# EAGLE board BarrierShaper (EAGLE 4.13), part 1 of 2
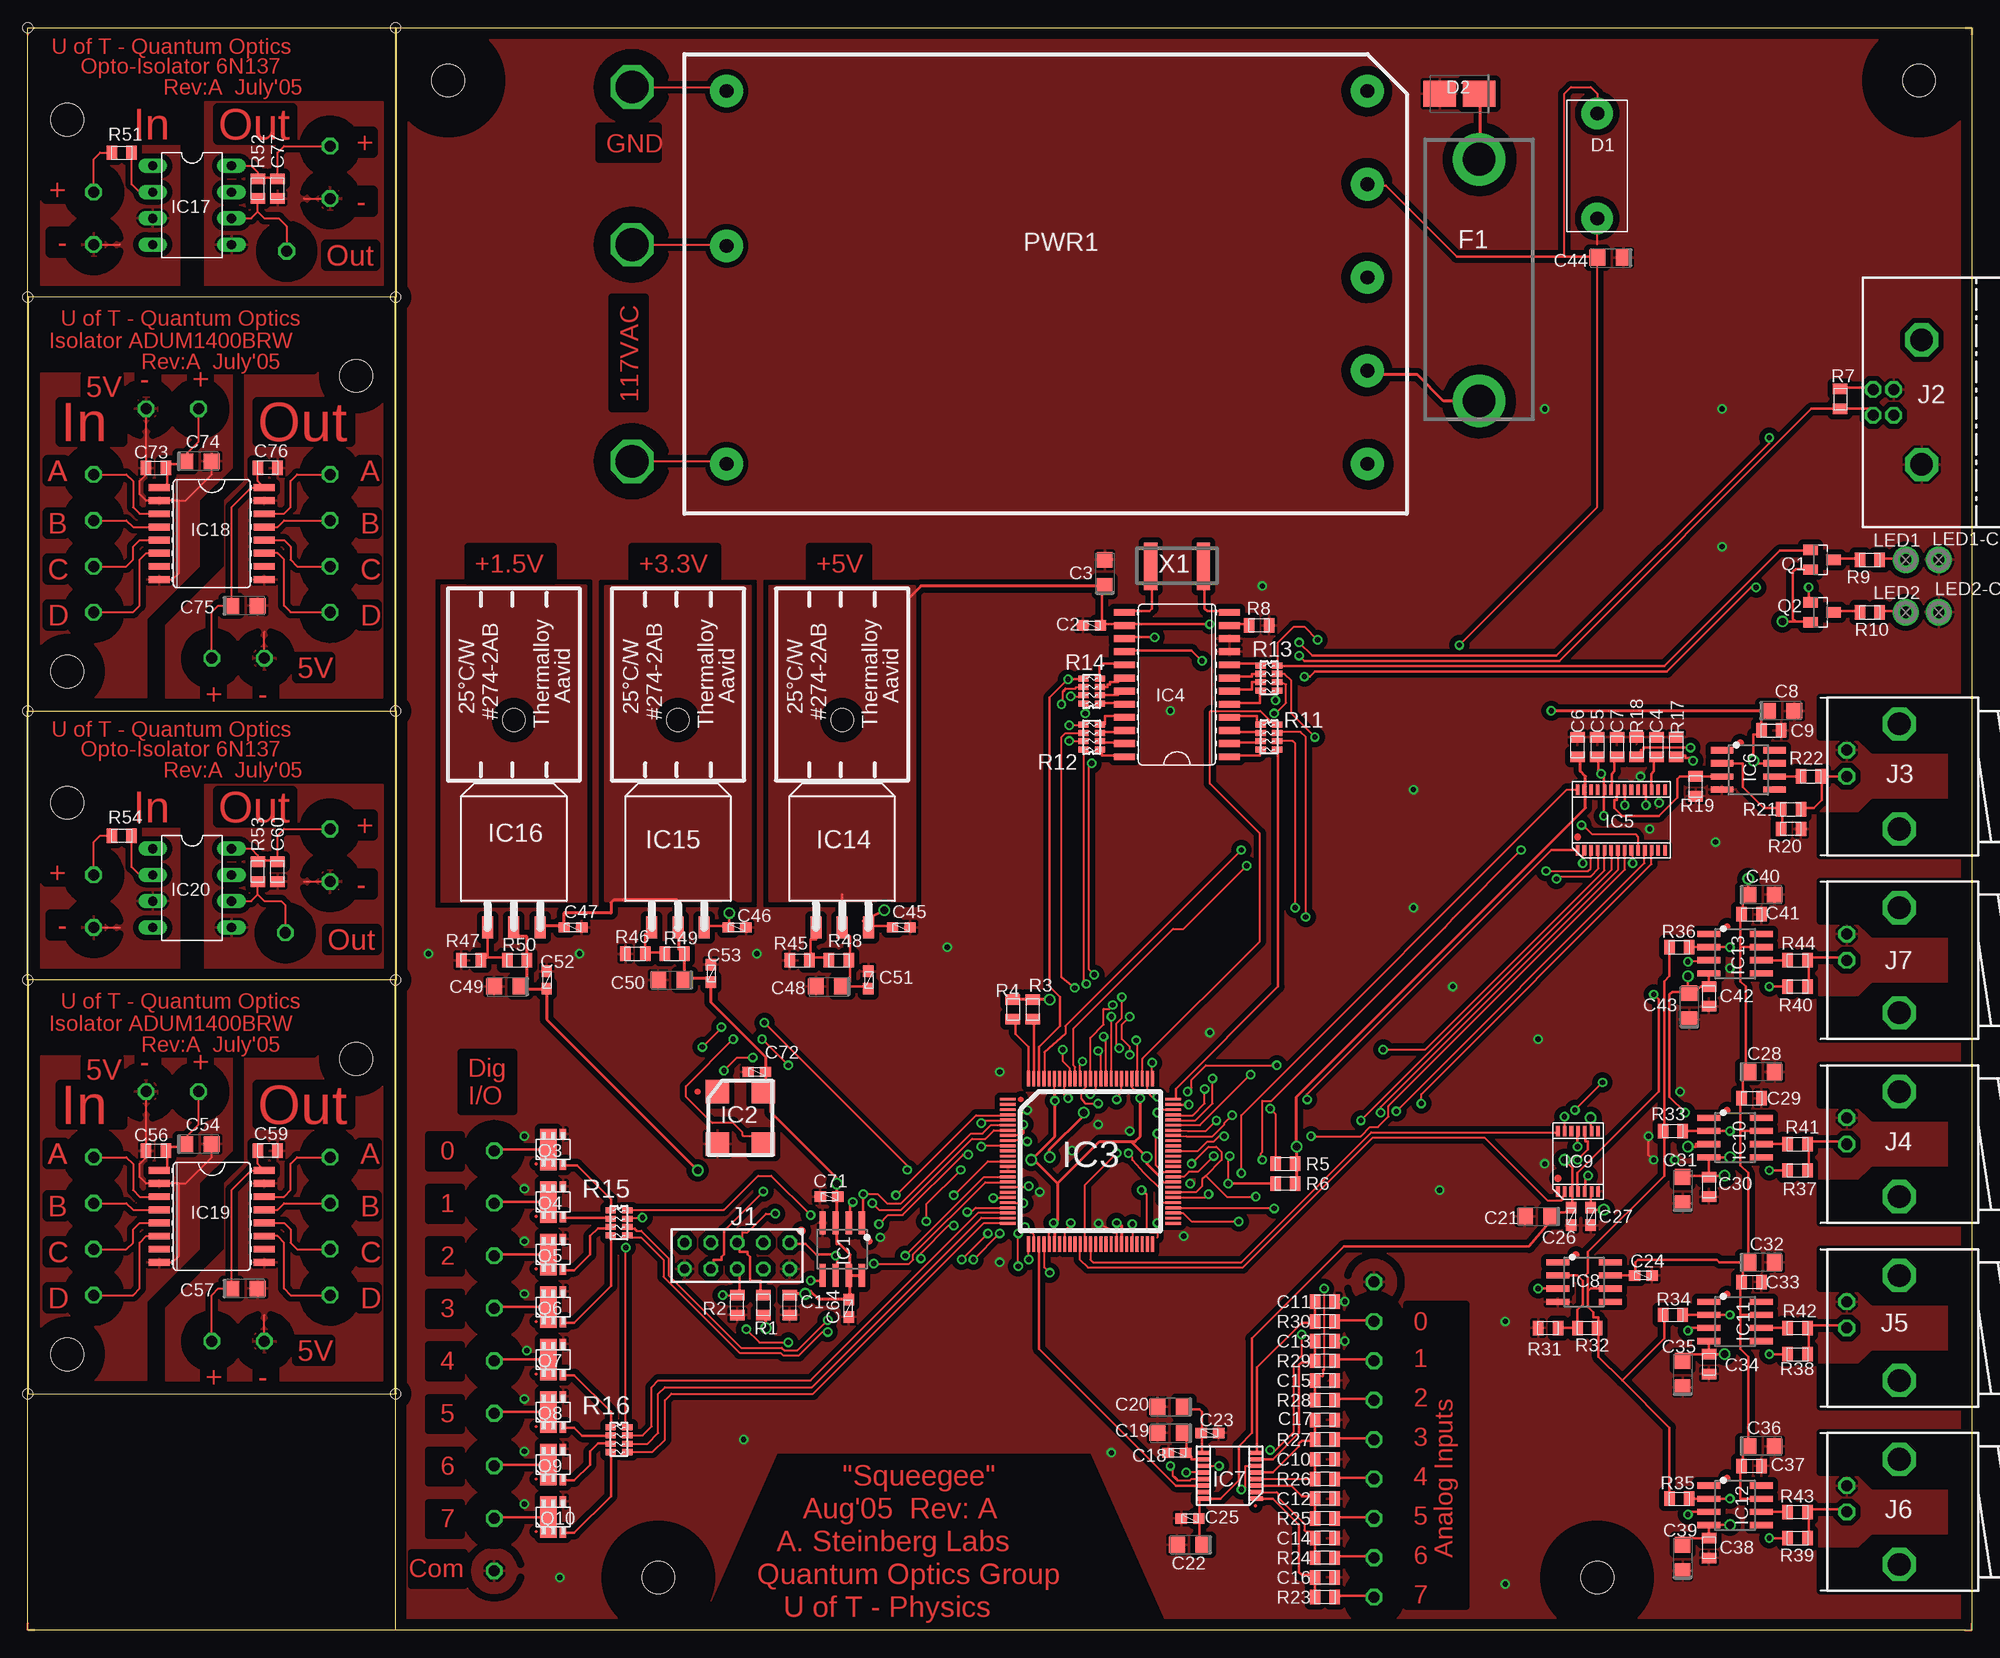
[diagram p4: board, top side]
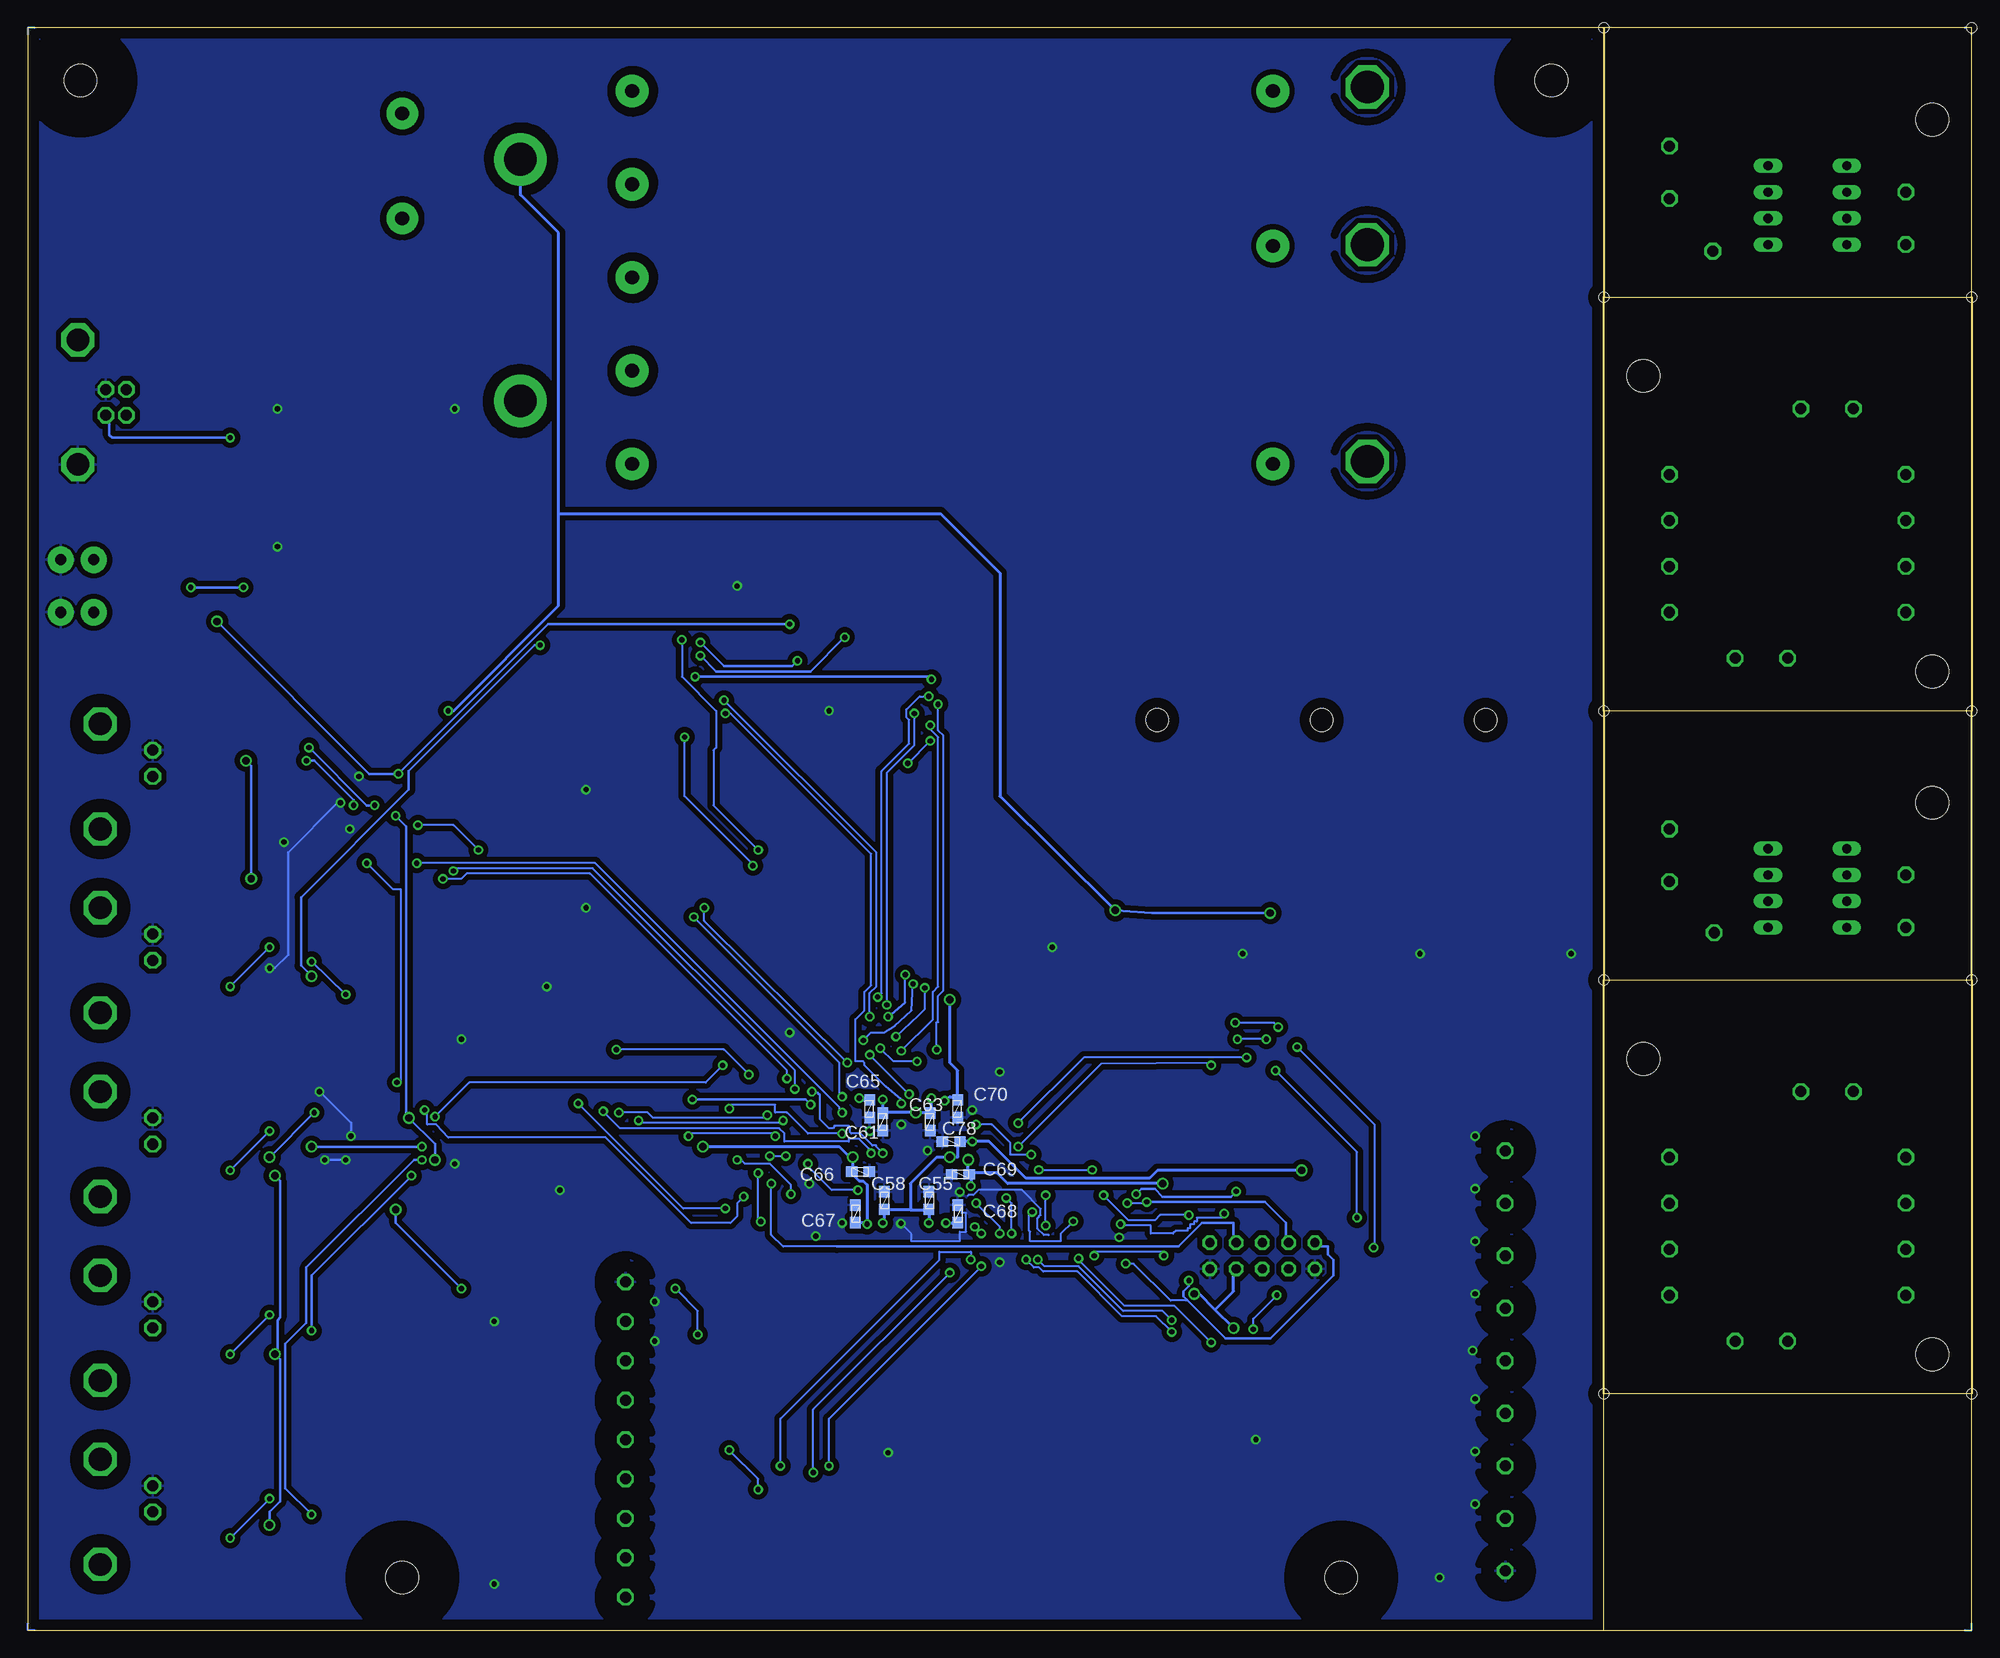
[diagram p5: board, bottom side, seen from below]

Size 187.96 x 154.94 mm. Coordinates in mm from the lower left corner, seen from the top.
Outline: 35.56,154.94 0,154.94 0,128.91
Outline: 35.56,154.94 35.56,128.91
Outline: 35.56,128.91 0,128.91
Outline: 0,128.91 0,88.9
Outline: 35.56,88.9 35.56,128.91
Outline: 35.56,0 35.56,154.94
Outline: 35.56,154.94 187.96,154.94 187.96,0 35.56,0
Outline: 0,88.9 35.56,88.9
Outline: 35.56,88.9 35.56,62.87
Outline: 35.56,62.87 0,62.87
Outline: 0,62.87 0,88.9
Outline: 0,62.87 0,22.86
Outline: 0,22.86 35.56,22.86 35.56,62.87
Outline: 35.56,0 0,0 0,22.86
Copper layers (1*16): Top 0.035mm / dielectric 1.5mm / Bottom 0.035mm
Design rules "DRC standard check (8mil trace and gap, etc)": minimum track width 8mil, minimum drill 20mil, track to track 8mil, track to pad 8mil, pad to pad 8mil, via to via 8mil, smd to smd 8mil, copper to edge 40mil, drill to drill 8mil, minimum pad ring 10mil, minimum via ring 8mil, stop-mask expansion 4mil, vias tented up to drill 0mil, thermal gap 10mil
Net classes: 0 default: width 0.203 mm, drill 0.203 mm, clearance 0.508 mm; 2 AC_Line: width 0.203 mm, drill 1.27 mm, clearance 0.711 mm; 3 Power: width 0.305 mm, drill 0.203 mm, clearance 0.711 mm
Holes 3.17 mm at 3.81,146.05 31.75,121.28 3.81,92.71 60.96,5.08 40.64,149.86 182.88,149.86 151.76,5.08 3.81,80.01 31.75,55.24 3.81,26.67
Holes 0.97 mm at 0,154.94 35.56,154.94 35.56,128.91 0,128.91 0,88.9 35.56,88.9 35.56,62.87 0,62.87 0,22.86 35.56,22.86
tRestrict: area 1,143.2 to 6.6,148.9; area 28.9,118.4 to 34.6,124.1; area 1,89.9 to 6.6,95.5; area 55.7,-0.2 to 66.2,10.3; area 35.4,144.6 to 45.9,155.1; area 177.6,144.6 to 188.1,155.1; area 146.5,-0.2 to 157,10.3; area 1,77.2 to 6.6,82.8; area 28.9,52.4 to 34.6,58.1; area 1,23.8 to 6.6,29.5; 106 lines
bRestrict: area 55.7,-0.2 to 66.2,10.3; area 35.4,144.6 to 45.9,155.1; area 177.6,144.6 to 188.1,155.1; area 146.5,-0.2 to 157,10.3; 31 lines

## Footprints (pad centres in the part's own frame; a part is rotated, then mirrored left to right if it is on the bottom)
TP-0.042 = drill 1.067 octagon: TP 0,0
TP-0.125 = drill 3.175 octagon: TP 0,0
0805 = smd 1.016 x 1.397: 1 -1.27,0; 2 0.635,0
0603 = smd 1.1 x 1: 1 -0.85,0; 2 0.85,0
EIA3216 = smd 1.524 x 1.524: + 0,0; - -2.54,0
PASSIVE_0.4" = drill 1.321 pad 3.048 round: 1 -5.08,0; 2 5.08,0
EIA-B(SMB) = smd 3.175 x 2.54: A- -1.905,0; K+ 1.905,0
FUSE_LITTLEFUSE05200002Z = drill 3.175 pad 5.08 round: 1 -11.938,0; 2 11.43,0
HEATSINK-3 = hole 2.184: 3.429,0
SOIC-8 = smd 0.6 x 2.2: 1 -1.27,-2.54; 2 0,-2.54; 3 1.27,-2.54; 4 2.54,-2.54; 5 2.54,2.54; 6 1.27,2.54; 7 0,2.54; 8 -1.27,2.54
CSX750(CITIZEN_OSC) = smd 2.286 x 2.286: 1 -2.54,-1.27; 2 2.54,-1.27; 3 2.54,3.175; 4 -2.54,3.175
TQFP-100 = smd 1.5 x 0.27: 1 -17,14.5; 2 -17,14; 3 -17,13.5; 4 -17,13; 5 -17,12.5; 6 -17,12; 7 -17,11.5; 8 -17,11; 9 -17,10.5; 10 -17,10; 11 -17,9.5; 12 -17,9; 13 -17,8.5; 14 -17,8; 15 -17,7.5; 16 -17,7; 17 -17,6.5; 18 -17,6; 19 -17,5.5; 20 -17,5; 21 -17,4.5; 22 -17,4; 23 -17,3.5; 24 -17,3; 25 -17,2.5; 51 -1,2.5; 52 -1,3; 53 -1,3.5; 54 -1,4; 55 -1,4.5; 56 -1,5; 57 -1,5.5; 58 -1,6; 59 -1,6.5; 60 -1,7; 61 -1,7.5; 62 -1,8; 63 -1,8.5; 64 -1,9; 65 -1,9.5; 66 -1,10; 67 -1,10.5; 68 -1,11; 69 -1,11.5; 70 -1,12; 71 -1,12.5; 72 -1,13; 73 -1,13.5; 74 -1,14; 75 -1,14.5 | smd 0.27 x 1.5: 26 -15,0.5; 27 -14.5,0.5; 28 -14,0.5; 29 -13.5,0.5; 30 -13,0.5; 31 -12.5,0.5; 32 -12,0.5; 33 -11.5,0.5; 34 -11,0.5; 35 -10.5,0.5; 36 -10,0.5; 37 -9.5,0.5; 38 -9,0.5; 39 -8.5,0.5; 40 -8,0.5; 41 -7.5,0.5; 42 -7,0.5; 43 -6.5,0.5; 44 -6,0.5; 45 -5.5,0.5; 46 -5,0.5; 47 -4.5,0.5; 48 -4,0.5; 49 -3.5,0.5; 50 -3,0.5; 76 -3,16.5; 77 -3.5,16.5; 78 -4,16.5; 79 -4.5,16.5; 80 -5,16.5; 81 -5.5,16.5; 82 -6,16.5; 83 -6.5,16.5; 84 -7,16.5; 85 -7.5,16.5; 86 -8,16.5; 87 -8.5,16.5; 88 -9,16.5; 89 -9.5,16.5; 90 -10,16.5; 91 -10.5,16.5; 92 -11,16.5; 93 -11.5,16.5; 94 -12,16.5; 95 -12.5,16.5; 96 -13,16.5; 97 -13.5,16.5; 98 -14,16.5; 99 -14.5,16.5; 100 -15,16.5
SOIC-24-0.3 = smd 0.66 x 2.032: 1 -6.35,-5.08; 2 -5.08,-5.08; 3 -3.81,-5.08; 4 -2.54,-5.08; 5 -1.27,-5.08; 6 0,-5.08; 7 1.27,-5.08; 8 2.54,-5.08; 9 3.81,-5.08; 10 5.08,-5.08; 11 6.35,-5.08; 12 7.62,-5.08; 13 7.62,5.08; 14 6.35,5.08; 15 5.08,5.08; 16 3.81,5.08; 17 2.54,5.08; 18 1.27,5.08; 19 0,5.08; 20 -1.27,5.08; 21 -2.54,5.08; 22 -3.81,5.08; 23 -5.08,5.08; 24 -6.35,5.08
TSSOP-28 = smd 0.356 x 1.016: 1 0,-5.85; 2 0.65,-5.85; 3 1.3,-5.85; 4 1.95,-5.85; 5 2.6,-5.85; 6 3.25,-5.85; 7 3.9,-5.85; 8 4.55,-5.85; 9 5.2,-5.85; 10 5.85,-5.85; 11 6.5,-5.85; 12 7.15,-5.85; 13 7.8,-5.85; 14 8.45,-5.85; 15 8.45,0; 16 7.8,0; 17 7.15,0; 18 6.5,0; 19 5.85,0; 20 5.2,0; 21 4.55,0; 22 3.9,0; 23 3.25,0; 24 2.6,0; 25 1.95,0; 26 1.3,0; 27 0.65,0; 28 0,0
SSOP-16 = smd 0.419 x 1.397: 1 -1.905,-2.54; 2 -1.27,-2.54; 3 -0.635,-2.54; 4 0,-2.54; 5 0.635,-2.54; 6 1.27,-2.54; 7 1.905,-2.54; 8 2.54,-2.54; 9 2.54,2.54; 10 1.905,2.54; 11 1.27,2.54; 12 0.635,2.54; 13 0,2.54; 14 -0.635,2.54; 15 -1.27,2.54; 16 -1.905,2.54
TSSOP-14 = smd 0.356 x 1.016: 1 0,-5.85; 2 0.65,-5.85; 3 1.3,-5.85; 4 1.95,-5.85; 5 2.6,-5.85; 6 3.25,-5.85; 7 3.9,-5.85; 8 3.9,0; 9 3.25,0; 10 2.6,0; 11 1.95,0; 12 1.3,0; 13 0.65,0; 14 0,0
TO263 = smd 1.067 x 2.159: 1 -2.54,0; 2 0,0; 3 2.54,0
DIL08 = drill 0.889 long: 1 -3.81,-3.81; 2 -1.27,-3.81; 3 1.27,-3.81; 4 3.81,-3.81; 5 3.81,3.81; 6 1.27,3.81; 7 -1.27,3.81; 8 -3.81,3.81
SOIC-16W = smd 0.66 x 2.032: 1 -6.35,-5.08; 2 -5.08,-5.08; 3 -3.81,-5.08; 4 -2.54,-5.08; 5 -1.27,-5.08; 6 0,-5.08; 7 1.27,-5.08; 8 2.54,-5.08; 9 2.54,5.08; 10 1.27,5.08; 11 0,5.08; 12 -1.27,5.08; 13 -2.54,5.08; 14 -3.81,5.08; 15 -5.08,5.08; 16 -6.35,5.08
CONN-2X5-BLASTER = drill 0.889 octagon: 1 0,5.08; 2 2.54,5.08; 3 0,2.54; 4 2.54,2.54; 5 0,0; 6 2.54,0; 7 0,-2.54; 8 2.54,-2.54; 9 0,-5.08; 10 2.54,-5.08
CONN-USB_AU-Y1007 = drill 1.067 octagon: 1 2.5,0; 2 0,0; 3 0,-2; 4 2.5,-2 | drill 2.184 octagon: S1 -4.75,-4.7; S2 7.3,-4.7
CONN-BNC-AMP-TYPE3HORIZ = drill 1.067 octagon: CONDUCTOR 0,-12.7; SHIELD -2.54,-12.7 | drill 2.184 octagon: P$1 -5.08,-7.62; P$2 5.08,-7.62
TP-HOLE = drill 1.067 pad 2.54 round: P$1 0,0
CUI_FSK15 = drill 1.321 pad 3.175 round: 1 -30.226,19.304; 2 -30.226,4.318; 3 -30.226,-16.764; 4 31.75,-16.764; 5 31.75,-7.747; 6 31.75,1.27; 7 31.75,10.287; 8 31.75,19.304
SOT23 = smd 1 x 1.4: 1 -0.953,-0.953; 2 0.953,-0.953; 3 0,1.27
SOT23-6MODIFIED = smd 1.575 x 4.013: 1 -0.46,1.387 | smd 0.635 x 0.991: 3 0.95,-0.099; 4 0.95,2.901
PANASONIC_EXB-V8V(QUAD-R-PACK) = smd 1 x 0.59: 1A -0.8,1.2; 1B 0.8,1.2; 2A -0.8,0.4; 2B 0.8,0.4; 3A -0.8,-0.4; 3B 0.8,-0.4; 4A -0.8,-1.2; 4B 0.8,-1.2
RESONATOR-P = smd 1.27 x 4.572: 1 -2.54,0; 2 2.54,0

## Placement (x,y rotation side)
+5V-IN  [TP-0.042]  16.51,118.11 90 top
+5V-IN1  [TP-0.042]  16.51,52.07 90 top
+5V-OUT  [TP-0.042]  17.78,93.98 270 top
+5V-OUT1  [TP-0.042]  17.78,27.94 270 top
AC1  [TP-0.125]  58.42,113.03 180 top
AC2  [TP-0.125]  58.42,133.99 180 top
ANS1  [TP-0.042]  130.18,3.17 0 top
ANS2  [TP-0.042]  130.18,6.99 0 top
ANS3  [TP-0.042]  130.18,10.79 0 top
ANS4  [TP-0.042]  130.18,14.61 0 top
ANS5  [TP-0.042]  130.18,18.41 0 top
ANS6  [TP-0.042]  130.18,22.23 0 top
ANS7  [TP-0.042]  130.18,26.04 0 top
ANS8  [TP-0.042]  130.18,29.84 0 top
ANS_COM  [TP-0.042]  130.18,33.66 0 top
C1  0.1uF  [0805]  73.66,31.75 90 top
C2  0.1uF  [0603]  102.87,97.16 0 top
C3  4.7uF  [EIA3216]  104.14,100.97 270 top
C4  0.1uF  [0805]  157.48,85.09 270 top
C5  0.1uF  [0805]  151.76,85.09 270 top
C6  0.1uF  [0805]  149.86,85.72 90 top
C7  0.1uF  [0805]  153.67,85.09 270 top
C8  4.7uF  [EIA3216]  168.28,88.9 180 top
C9  0.1uF  [0805]  168.91,87 0 top
C10  0.1uF  [0805]  125.09,16.51 180 top
C11  0.1uF  [0805]  125.09,31.75 180 top
C12  0.1uF  [0805]  125.09,12.7 180 top
C13  0.1uF  [0805]  125.09,27.94 180 top
C14  0.1uF  [0805]  125.09,8.89 180 top
C15  0.1uF  [0805]  125.09,24.13 180 top
C16  0.1uF  [0805]  125.09,5.08 180 top
C17  0.1uF  [0805]  125.09,20.32 180 top
C18  0.1uF  [0603]  111.12,17.14 0 top
C19  4.7uF  [EIA3216]  111.76,19.05 0 top
C20  4.7uF  [EIA3216]  111.76,21.59 0 top
C21  4.7uF  [EIA3216]  147.32,40.01 0 top
C22  4.7uF  [EIA3216]  113.67,8.26 0 top
C23  0.1uF  [0603]  114.3,19.05 180 top
C24  0.1uf  [0603]  156.21,34.29 180 top
C25  0.1uf  [0603]  112.39,10.79 180 top
C26  0.1uf  [0603]  149.22,40.01 270 top
C27  0.1uF  [0603]  151.13,40.01 270 top
C28  4.7uF  [EIA3216]  166.37,53.98 180 top
C29  0.1uF  [0805]  167,51.44 0 top
C30  0.1uF  [0805]  162.56,42.55 270 top
C31  4.7uF  [EIA3216]  160.02,41.27 270 top
C32  4.7uF  [EIA3216]  166.37,35.56 180 top
C33  0.1uF  [0805]  167,33.66 0 top
C34  0.1uF  [0805]  162.56,25.4 270 top
C35  4.7uF  [EIA3216]  160.02,23.5 270 top
C36  4.7uF  [EIA3216]  166.37,17.78 180 top
C37  0.1uF  [0805]  167,15.88 0 top
C38  0.1uF  [0805]  162.56,7.62 270 top
C39  4.7uF  [EIA3216]  160.02,5.71 270 top
C40  4.7uF  [EIA3216]  166.37,71.12 180 top
C41  0.1uF  [0805]  167,69.22 0 top
C42  0.1uF  [0805]  162.56,60.96 270 top
C43  4.7uF  [EIA3216]  160.66,59.05 270 top
C44  4.7uF  [EIA3216]  154.31,132.72 0 top
C45  0.1uF  [0603]  84.45,67.94 180 top
C46  0.1uF  [0603]  68.58,67.94 180 top
C47  0.1uF  [0603]  52.7,67.94 180 top
C48  4.7uF  [EIA3216]  78.74,62.23 0 top
C49  4.7uF  [EIA3216]  47.62,62.23 0 top
C50  4.7uF  [EIA3216]  63.5,62.87 0 top
C51  0.1uF  [0603]  81.28,62.87 270 top
C52  0.1uF  [0603]  50.16,62.87 270 top
C53  0.1uF  [0603]  66.04,63.5 270 top
C54  4.7uF  [EIA3216]  15.24,46.99 180 top
C55  0.1uF  [0603]  100.84,41.53 270 bottom
C56  0.1uF  [0805]  12.7,46.35 0 top
C57  4.7uF  [EIA3216]  19.68,33.02 180 top
C58  0.1uF  [0603]  105.16,41.53 270 bottom
C59  0.1uF  [0805]  22.86,46.35 180 top
C60  0.1uF  [0805]  24.13,73.66 90 top
C61  0.1uF  [0603]  105.28,49.15 90 bottom
C63  0.1uF  [0603]  100.71,49.15 90 bottom
C64  0.1uF  [0603]  79.38,31.11 90 top
C65  0.1uF  [0603]  106.55,50.42 90 bottom
C66  0.1uF  [0603]  107.44,44.32 180 bottom
C67  0.1uF  [0603]  107.95,40.26 270 bottom
C68  0.1uF  [0603]  98.04,40.26 270 bottom
C69  0.1uF  [0603]  97.79,44.07 0 bottom
C70  0.1uF  [0603]  98.04,50.42 90 bottom
C71  0.1uF  [0603]  77.47,41.91 0 top
C72  0.1uF  [0603]  70.48,53.98 0 top
C73  0.1uF  [0805]  12.7,112.39 0 top
C74  4.7uF  [EIA3216]  15.24,113.03 180 top
C75  4.7uF  [EIA3216]  19.68,99.06 180 top
C76  0.1uF  [0805]  22.86,112.39 180 top
C77  0.1uF  [0805]  24.13,139.7 90 top
C78  0.1uF  [0603]  98.68,47.24 0 bottom
COM-IN  [TP-0.042]  11.43,118.11 90 top
COM-IN1  [TP-0.042]  29.21,143.51 0 top
COM-IN2  [TP-0.042]  25.02,133.35 270 top
COM-IN3  [TP-0.042]  29.21,138.43 0 top
COM-IN4  [TP-0.042]  11.43,52.07 90 top
COM-IN5  [TP-0.042]  29.21,77.47 0 top
COM-IN6  [TP-0.042]  24.89,67.44 270 top
COM-IN7  [TP-0.042]  29.21,72.39 0 top
COM-OUT  [TP-0.042]  22.86,93.98 270 top
COM-OUT1  [TP-0.042]  22.86,27.94 270 top
D1  1N5343B  [PASSIVE_0.4"]  151.76,141.6 270 top
D2  1N4004WDICT  [EIA-B(SMB)]  138.43,148.59 0 top
DIGO0  [TP-0.042]  45.09,46.35 180 top
DIGO1  [TP-0.042]  45.09,41.27 180 top
DIGO2  [TP-0.042]  45.09,36.2 180 top
DIGO3  [TP-0.042]  45.09,31.11 180 top
DIGO4  [TP-0.042]  45.09,26.04 180 top
DIGO5  [TP-0.042]  45.09,20.95 180 top
DIGO6  [TP-0.042]  45.09,15.88 180 top
DIGO7  [TP-0.042]  45.09,10.79 180 top
DIGOCOM  [TP-0.042]  45.09,5.71 180 top
F1  1A  [FUSE_LITTLEFUSE05200002Z]  140.34,130.81 90 top
GND  [TP-0.125]  58.42,149.22 180 top
HS1  Wakefield 274-2AB  [HEATSINK-3]  46.99,91.44 270 top
HS2  Wakefield 274-2AB  [HEATSINK-3]  62.87,91.44 270 top
HS3  Wakefield 274-2AB  [HEATSINK-3]  78.74,91.44 270 top
IC1  EPCS4  [SOIC-8]  79.38,36.83 180 top
IC2  100MHz  [CSX750(CITIZEN_OSC)]  67.94,49.53 270 top
IC3  EP1C3T100C6  [TQFP-100]  111.76,36.83 0 top
IC4  802600(DELCOM-USB)-SOIC24  [SOIC-24-0.3]  111.12,90.81 90 top
IC5  AD9752ARU  [TSSOP-28]  149.86,81.28 0 top
IC6  AD8065AR  [SOIC-8]  166.37,83.82 270 top
IC7  LTC1867ACGN  [SSOP-16]  116.2,14.61 90 top
IC8  AD8065AR  [SOIC-8]  150.5,34.29 270 top
IC9  [TSSOP-14]  147.96,48.26 0 top
IC10  AD8065AR  [SOIC-8]  165.1,48.26 270 top
IC11  AD8065AR  [SOIC-8]  165.1,30.48 270 top
IC12  AD8065AR  [SOIC-8]  165.1,12.7 270 top
IC13  AD8065AR  [SOIC-8]  165.1,66.04 270 top
IC14  LM1086CS-adj  [TO263]  78.74,67.94 0 top
IC15  LM1086CS-adj  [TO263]  62.87,67.94 0 top
IC16  LM1086-adj  [TO263]  46.99,67.94 0 top
IC17  6N137  [DIL08]  15.88,137.79 270 top
IC18  ADUM1400BRW  [SOIC-16W]  17.78,104.14 270 top
IC19  ADUM1400BRW  [SOIC-16W]  17.78,38.1 270 top
IC20  6N137  [DIL08]  15.88,71.75 270 top
IN1  [TP-0.042]  6.35,111.76 180 top
IN2  [TP-0.042]  6.35,107.31 180 top
IN3  [TP-0.042]  6.35,102.87 180 top
IN4  [TP-0.042]  6.35,98.42 180 top
IN5  [TP-0.042]  6.35,45.72 180 top
IN6  [TP-0.042]  6.35,41.27 180 top
IN7  [TP-0.042]  6.35,36.83 180 top
IN8  [TP-0.042]  6.35,32.38 180 top
IN+  [TP-0.042]  6.35,139.06 270 top
IN+1  [TP-0.042]  6.35,73.03 270 top
IN-  [TP-0.042]  6.35,133.99 180 top
IN-1  [TP-0.042]  6.35,67.94 180 top
J1  [CONN-2X5-BLASTER]  68.58,37.47 270 top
J2  [CONN-USB_AU-Y1007]  178.44,117.47 90 top
J3  "Fast DAC"  [CONN-BNC-AMP-TYPE3HORIZ]  188.59,82.55 270 top
J4  "Slow DAC 2"  [CONN-BNC-AMP-TYPE3HORIZ]  188.59,46.99 270 top
J5  "Slow DAC 3"  [CONN-BNC-AMP-TYPE3HORIZ]  188.59,29.21 270 top
J6  "Slow DAC 4"  [CONN-BNC-AMP-TYPE3HORIZ]  188.59,11.43 270 top
J7  "Slow DAC 1"  [CONN-BNC-AMP-TYPE3HORIZ]  188.59,64.77 270 top
LED1  [TP-HOLE]  181.61,103.5 0 top
LED1-COM  [TP-HOLE]  184.78,103.5 0 top
LED2  [TP-HOLE]  181.61,98.42 0 top
LED2-COM  [TP-HOLE]  184.78,98.42 0 top
OUT1  [TP-0.042]  29.21,111.76 0 top
OUT2  [TP-0.042]  29.21,107.31 0 top
OUT3  [TP-0.042]  29.21,102.87 0 top
OUT4  [TP-0.042]  29.21,98.42 0 top
OUT5  [TP-0.042]  29.21,45.72 0 top
OUT6  [TP-0.042]  29.21,41.27 0 top
OUT7  [TP-0.042]  29.21,36.83 0 top
OUT8  [TP-0.042]  29.21,32.38 0 top
PWR1  FSK-S15-15U  [CUI_FSK15]  97.79,129.54 0 top
Q1  IRLML5103  [SOT23]  173.35,103.5 270 top
Q2  IRLML5103  [SOT23]  173.35,98.42 270 top
Q3  [SOT23-6MODIFIED]  50.8,45.09 0 top
Q4  [SOT23-6MODIFIED]  50.8,40.01 0 top
Q5  [SOT23-6MODIFIED]  50.8,34.92 0 top
Q6  [SOT23-6MODIFIED]  50.8,29.84 0 top
Q7  [SOT23-6MODIFIED]  50.8,24.77 0 top
Q8  [SOT23-6MODIFIED]  50.8,19.68 0 top
Q9  [SOT23-6MODIFIED]  50.8,14.61 0 top
Q10  [SOT23-6MODIFIED]  50.8,9.53 0 top
R1  10K  [0805]  71.12,31.11 270 top
R2  10K  [0805]  68.58,31.75 90 top
R3  10K  [0805]  97.16,59.69 270 top
R4  10K  [0805]  95.25,59.69 270 top
R5  10K  [0805]  121.92,45.09 0 top
R6  10K  [0805]  121.92,43.18 0 top
R7  7.50K  [0805]  175.26,118.75 270 top
R8  7.50K  [0805]  118.75,97.16 180 top
R9  1K  [0805]  178.44,103.5 0 top
R10  1K  [0805]  178.44,98.42 0 top
R11  1K  [PANASONIC_EXB-V8V(QUAD-R-PACK)]  120.02,86.36 0 top
R12  1K  [PANASONIC_EXB-V8V(QUAD-R-PACK)]  102.87,86.36 180 top
R13  1K  [PANASONIC_EXB-V8V(QUAD-R-PACK)]  120.02,92.08 0 top
R14  1K  [PANASONIC_EXB-V8V(QUAD-R-PACK)]  102.87,90.81 180 top
R15  1K  [PANASONIC_EXB-V8V(QUAD-R-PACK)]  57.15,39.37 0 top
R16  1K  [PANASONIC_EXB-V8V(QUAD-R-PACK)]  57.15,18.41 0 top
R17  3.92K  [0805]  159.38,85.09 270 top
R18  49.9  [0805]  155.57,85.09 270 top
R19  49.9  [0805]  161.29,81.92 90 top
R20  49.9  [0805]  170.18,77.47 180 top
R21  499  [0805]  170.81,79.38 0 top
R22  49.9  [0805]  172.72,82.55 0 top
R23  1K  [0805]  125.09,3.17 180 top
R24  1K  [0805]  125.09,6.99 180 top
R25  1K  [0805]  125.09,10.79 180 top
R26  1K  [0805]  125.09,14.61 180 top
R27  1K  [0805]  125.09,18.41 180 top
R28  1K  [0805]  125.09,22.23 180 top
R29  1K  [0805]  125.09,26.04 180 top
R30  1K  [0805]  125.09,29.84 180 top
R31  499  [0805]  147.32,29.21 0 top
R32  499  [0805]  151.13,29.21 0 top
R33  499  [0805]  159.38,48.26 0 top
R34  499  [0805]  159.38,30.48 0 top
R35  499  [0805]  160.02,12.7 0 top
R36  499  [0805]  160.02,66.04 0 top
R37  499  [0805]  171.45,44.45 0 top
R38  499  [0805]  171.45,26.67 0 top
R39  499  [0805]  171.45,8.89 0 top
R40  499  [0805]  171.45,62.23 0 top
R41  49.9  [0805]  171.45,46.99 0 top
R42  49.9  [0805]  171.45,29.21 0 top
R43  49.9  [0805]  171.45,11.43 0 top
R44  49.9  [0805]  171.45,64.77 0 top
R45  365  [0805]  74.93,64.77 0 top
R46  200  [0805]  59.05,65.41 0 top
R47  24.9  [0805]  43.18,64.77 0 top
R48  121  [0805]  78.74,64.77 0 top
R49  121  [0805]  62.87,65.41 0 top
R50  121  [0805]  47.62,64.77 0 top
R51  499  [0805]  9.4,142.88 0 top
R52  10K  [0805]  22.23,139.7 90 top
R53  10K  [0805]  22.23,73.66 90 top
R54  499  [0805]  9.4,76.83 0 top
U$81  [TARGET]  not placed on the board
U$82  [TARGET]  not placed on the board
U$83  [TARGET]  not placed on the board
U$84  [TITLEBLOCK_PCB]  not placed on the board
X1  6MHz  [RESONATOR-P]  111.12,102.87 0 top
